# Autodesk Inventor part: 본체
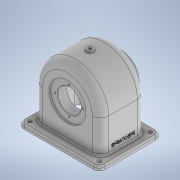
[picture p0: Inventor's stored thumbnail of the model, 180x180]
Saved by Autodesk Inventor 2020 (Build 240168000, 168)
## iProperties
Created: 2022-09
Part Number: 본체
Material: 일반
Document SubType Name: Modeling
Designer: Administrator
Density: 1 g/cm^3
Appearance: 기본값
Mass: 366.804 g
Surface Area: 1047.47 cm^2
Volume: 366.804 cm^3
Author: Administrator
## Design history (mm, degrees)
sketch "스케치1"
  geometry: L1 (-70, 54)-(70, 54); L2 (70, 54)-(70, -54); L3 (70, -54)-(-70, -54); L4 (-70, -54)-(-70, 54); L5 (-70, 54)-(70, -54); L6 (70, 54)-(-70, -54); 1 further point
  constraints: 12 end point, 2 midpoint, 2 parallel, 1 horizontal, 1 perpendicular
  dimensions: "d0" = 140 distance of L1.start L1.end; "d1" = 108 distance of L3.end L1.start
extrude "돌출1" new body sketch "스케치1" distance "d2" = 7; taper "d3" = 0 deg
sketch "스케치2"
  geometry: L1 (-70, 0)-(70, 0) reference; L2 (-70, 7)-(70, 7) reference; L3 (57, 64)-(57, 7); L4 (-57, 64)-(-57, 7); A1 r 57 centre (0, 64) between (57, 64) and (-57, 64); 1 further point
  constraints: 4 end point, 2 perpendicular, 2 point on circle, 2 point on line, 2 tangent, 1 centre point, 1 vertical alignment
  dimensions: "d4" = 114 diameter of A1; "d5" = 64 distance from line of A1.centre L1
extrude "돌출2" join sketch "스케치2" stored distance "d6" = 78; taper "d7" = 0 deg
node "작업 평면1"
sketch "스케치3"
  geometry: L1 (-70, 0)-(70, 0) reference; C1 r 31 at (0, 64); 2 further points
  constraints: 1 centre point, 1 midpoint, 1 vertical alignment
  dimensions: "d9" = 62 diameter of C1; "d10" = 64 distance from line of C1.centre L1
extrude "돌출3" join sketch "스케치3" stored distance "d11" = 78; taper "d12" = 0 deg
sketch "스케치4"
  geometry: C1 r 31 at (0, 0) reference; 2 further points
  constraints: 1 coincident
hole "구멍1" sketch "스케치4" at (0, 0) diameter "d13" = 40; stored, may be unused: countersink angle "d17" = 90 deg, drill point angle "d19" = 0 deg; dims "d14" = 6, "d15" = 8, "d16" = 4.4, "d18" = 16
fillet "모깎기1" dims "d20" = 14
fillet "모깎기2" dims "d21" = 10
sketch "스케치6"
  geometry: L1 (34, 64)-(34, 0); L2 (44, 0)-(-44, 0) reference; L3 (-34, 27.917)-(-34, 0); L4 (39, 107)-(39, 64) reference; L5 (-25, 121)-(25, 121) reference; L6 (-39, 64)-(-39, 107) reference; L7 (54, 84)-(54, 44) reference; L8 (54, 64)-(-93.267, 64); L9 (-20, 64)-(-20, 36); L10 (-20, 36)-(-34, 27.917); L11 (-39, 7)-(-39, 64) reference; 1 further point
  constraints: 10 end point, 4 point on line, 1 horizontal, 1 midpoint, 1 vertical
  dimensions: "d22" = 5 distance between parallel lines of L1 L4; "d36" = 56 diameter of L9.end L8; "d38" = 60 deg angle of L10 L9; "d39" = 14 distance between parallel lines of L9 L3; "d40" = 5 distance between parallel lines of L3 L11
extrude "돌출5" cut sketch "스케치6" stored distance "d41" = 68; taper "d42" = 0 deg
sketch "스케치7"
  geometry: L1 (34, 64)-(-34, 64) reference; L2 (-34, 64)-(-52, 64); L3 (-57, 64)-(-43, 64) reference; L4 (34, 64)-(52, 64); L5 (57, 64)-(43, 64) reference; A1 r 52 centre (0, 64) between (52, 64) and (-52, 64); 1 further point
  constraints: 4 end point, 2 point on circle, 2 point on line, 1 centre point, 1 midpoint
  dimensions: "d43" = 104 diameter of A1
extrude "돌출6" cut sketch "스케치7" stored distance "d44" = 68; taper "d45" = 0 deg
sketch "스케치8"
  geometry: L1 (-20, 36)-(-20, 64) reference; L2 (-20, 64)-(-20, 92); L3 (-20, 92)-(-34, 100.083); L4 (-34, 116)-(-34, 64) reference; L5 (54, 84)-(54, 44) reference; L6 (-34, 64)-(34, 64) reference; L7 (54, 64)-(-76.943, 64); L8 (-34, 27.917)-(-20, 36) reference; L9 (-34, 0)-(-34, 27.917) reference; L10 (-34, 64)-(-34, 27.917); L11 (-25, 64)-(-25, 7) reference; 1 further point
  constraints: 8 end point, 1 horizontal, 1 midpoint, 1 parallel, 1 point on line, 1 vertical
  dimensions: "d47" = 56 distance of L2.end L1.start; "d48" = 60 deg angle of L2 L3
sketch "스케치9"
  geometry: C1 r 20 at (0, 0) reference; 2 further points
  constraints: 1 coincident
hole "구멍2" sketch "스케치9" at (0, 0) diameter "d52" = 35; stored, may be unused: countersink angle "d56" = 90 deg, drill point angle "d58" = 0 deg; dims "d53" = 6, "d54" = 8, "d55" = 4.4, "d57" = 16
sketch "스케치10"
  geometry: A1 r 43 centre (0, 64) between (43, 64) and (-43, 64) reference; 1 further point
fillet "모깎기5" dims "d70" = 0.6
extrude "돌출8" cut sketch "스케치8" stored distance "d71" = 68; taper "d72" = 0 deg
revolve "회전1" stored, may be unused: angle "d73" = 90 deg
fillet "모깎기6" dims "d74" = 3
hole "구멍4" sketch "스케치10" diameter "d75" = 40; stored, may be unused: countersink angle "d79" = 90 deg, drill point angle "d81" = 0 deg; dims "d76" = 6, "d77" = 64, "d78" = 3, "d80" = 16
chamfer "모따기2" distance "d82" = 1; stored, may be unused: second distance "d83" = 2, angle "d84" = 45 deg
fillet "모깎기7" dims "d85" = 3
sketch "스케치11"
  geometry: L1 (60, 0)-(-60, 0) reference; L2 (-35.217, 64)-(-37.815, 64) reference; L3 (-34, 47.448)-(-34, 0) reference; L4 (-34, 47.448)-(-34, 54.822) reference; L5 (-34, 54.822)-(-34, 64) reference; L6 (-34, 64)-(-35.217, 64) reference; L7 (34, 0)-(34, 47.448) reference; L8 (34, 54.822)-(34, 47.448) reference; L9 (34, 64)-(34, 54.822) reference; L10 (35.217, 64)-(34, 64) reference; L11 (37.815, 64)-(35.217, 64) reference; L12 (34, 64)-(52, 64) reference; L13 (52, 64)-(52, 0); L14 (-60, 0)-(60, 0) reference; L15 (-52, 64)-(-34, 64) reference; L16 (-52, 64)-(-52, 0); 2 further points
  constraints: 4 end point, 2 perpendicular, 2 point on line
extrude "돌출9" cut sketch "스케치11" stored distance "d86" = 68; taper "d87" = 0 deg
fillet "모깎기8" dims "d88" = 9
node "작업 평면2"
sketch "스케치12"
  geometry: C1 r 6 at (0, 0); 1 further point
  constraints: 1 centre point, 1 coincident
  dimensions: "d90" = 12 diameter of C1
extrude "돌출10" join sketch "스케치12" stored distance "d91" = 68; taper "d92" = 0 deg
sketch "스케치13"
  geometry: C1 r 6 at (0, 0) reference; 2 further points
  constraints: 1 coincident
hole "구멍5" sketch "스케치13" at (0, 0) diameter "d93" = 5.1881; stored, may be unused: countersink angle "d97" = 90 deg, drill point angle "d99" = 0 deg; dims "d94" = 12, "d95" = 64, "d96" = 3, "d98" = 16
fillet "모깎기9" dims "d100" = 1
sketch "스케치14"
  geometry: C1 r 31 at (0, 0) reference; 2 further points
  constraints: 1 vertical alignment
  dimensions: "d101" = 24 distance of point (0, -24) C1.centre
hole "구멍6" sketch "스케치14" at (0, -24) diameter "d102" = 2.459; stored, may be unused: countersink angle "d106" = 90 deg, drill point angle "d108" = 118 deg; dims "d103" = 7, "d104" = 64, "d105" = 3, "d107" = 9
sketch "스케치15"
  geometry: C1 r 32 at (0, 0) reference; 2 further points
  constraints: 1 vertical alignment
  dimensions: "d112" = 24 distance of point (0, 24) C1.centre
hole "구멍7" sketch "스케치15" at (0, 24) diameter "d113" = 2.459; stored, may be unused: countersink angle "d117" = 90 deg, drill point angle "d119" = 118 deg; dims "d114" = 7, "d115" = 64, "d116" = 3, "d118" = 9
sketch "스케치16"
  geometry: L1 (0, -14)-(57, -14) reference; L2 (64, -19)-(64, 69) reference; 2 further points
  constraints: 1 other
  dimensions: "d123" = 39 distance from line of point (47, 25) L1; "d124" = 17 distance from line of point (47, 25) L2
feature "엠보싱1" sketch "스케치16" dims "d125" = 0.5, "d126" = 0
sketch "스케치17"
  geometry: A1 r 10 centre (60, -44) between (60, -54) and (70, -44) reference; 2 further points
  constraints: 1 coincident
hole "구멍8" sketch "스케치17" at (60, -44) diameter "d127" = 6.6; stored, may be unused: countersink angle "d131" = 90 deg, drill point angle "d133" = 0 deg; dims "d128" = 7, "d129" = 64, "d130" = 3, "d132" = 9
fillet "모깎기10" dims "d138" = 3
fillet "모깎기11" dims "d139" = 3
node "솔리드1"
pattern_circular "원형 패턴1" dims angle "d110" = 360 deg
pattern_circular "원형 패턴2" dims angle "d121" = 360 deg
pattern_linear "직사각형 패턴1"
feature "A9D066F2-1C7D-4E18-AEED-F7BC21143FA4" dims "d13" = 40, "d14" = 6, "d15" = 8, "d16" = 4.4, "d17" = 90 deg, "d18" = 16, "d19" = 0
other parameters: "d8" = 54, "d89" = 124
